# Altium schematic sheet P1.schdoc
size 420 x 297 mm; Width: 1655; Height: 1170; Symbol: Drawing-Symbol_A4; Company: 嘉立创EDA; Version: V1.0; Page Size: A4; @Project Name: C-T光谱仪; @Update Date: 2026-05-10; @Create Date: 2026-05-10; Device: Drawing-Symbol_A4; @Board Name: Board1; @Page Name: P1; @Create Time: 16:10:01; @Page Count: 1; @Page No: 1; @Schematic Name: Schematic2; @Update Time: 16:10:01; @Assembly Variant: Basic; Border: 1; Title Block Position: 3; Size: A4; Region Start: 1; X Region Count: 6; Y Region Count: 4; Blade Width: 10
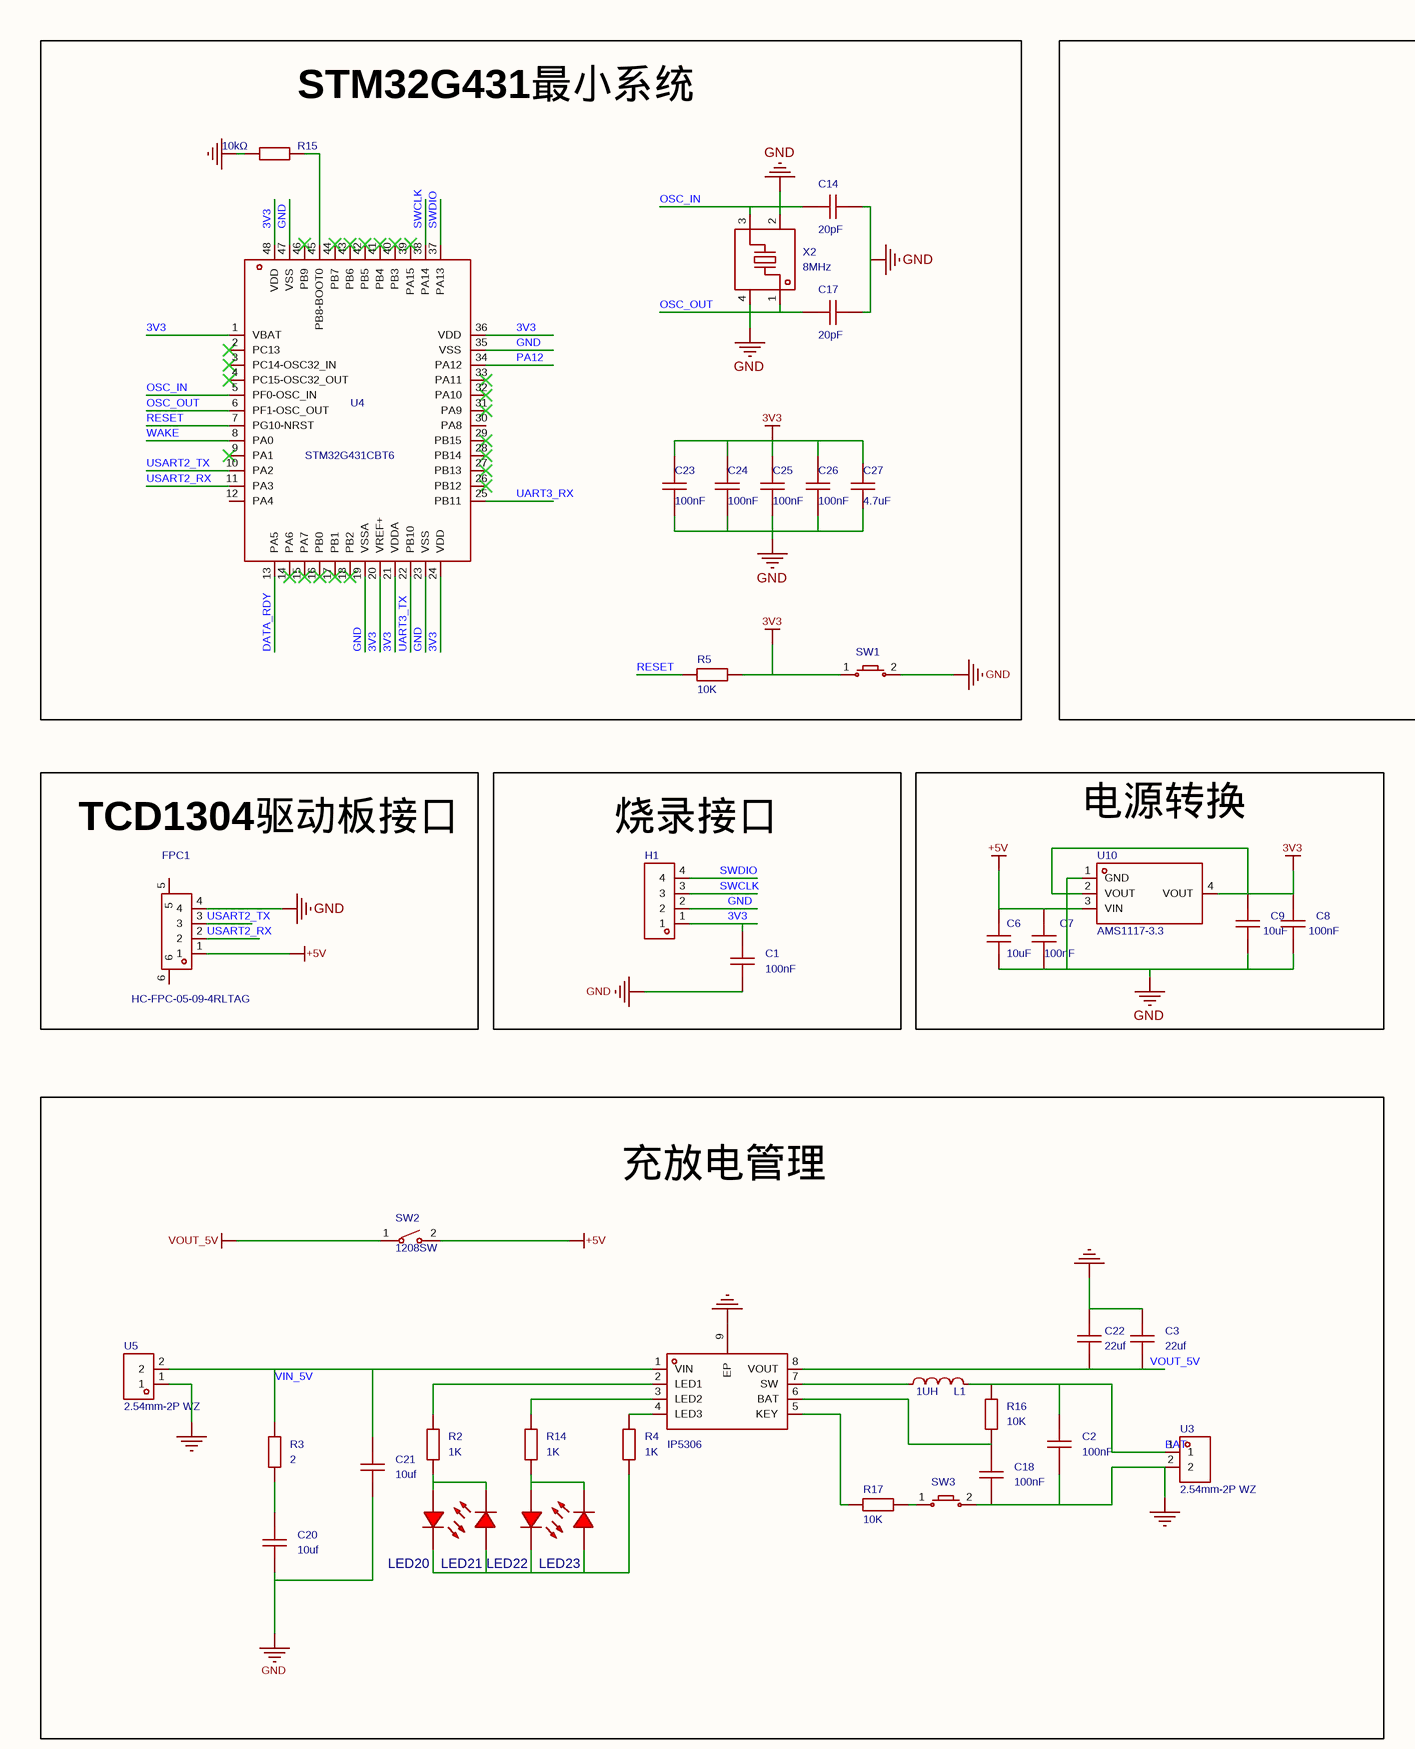
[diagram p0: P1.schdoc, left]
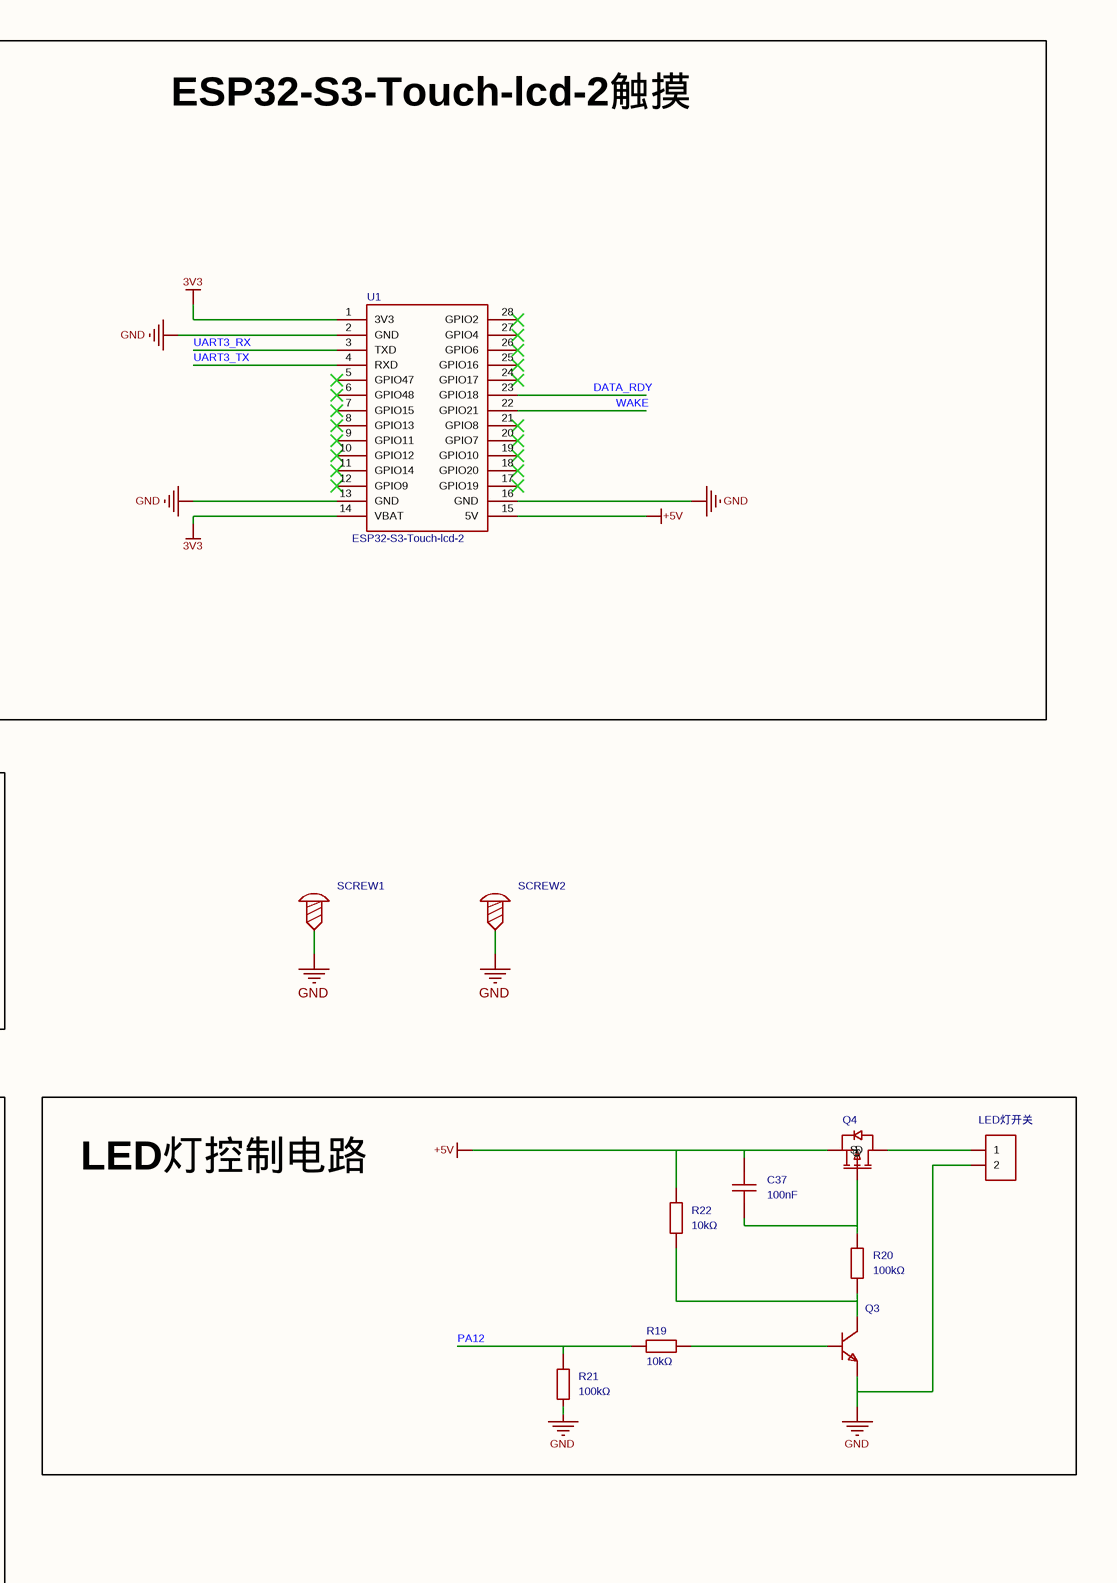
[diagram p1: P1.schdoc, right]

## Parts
C1  100nF  [C0805]
C2  100nF  [C0805]
C3  22uf  [C0805]
C6  10uF  [C0805]
C7  100nF  [C0805]
C8  100nF  [C0805]
C9  10uF  [C0805]
C14  20pF  [C0805]
C17  20pF  [C0805]
C18  100nF  [C0805]
C20  10uf  [C0805]
C21  10uf  [C0805]
C22  22uf  [C0805]
C23  100nF  [C0805]
C24  100nF  [C0805]
C25  100nF  [C0805]
C26  100nF  [C0805]
C27  4.7uF  [C0805]
C37  100nF  [C0805]
FPC1  HC-FPC-05-09-4RLTAG  [FPC-SMD_4P-P0.50_HC-FPC-05-09-4RLTAG]
H1  (no value)  [HDR-TH_4P-P2.54-V-M]
L1  1UH  [IND-SMD_L7.0-W6.6_CMKD-0630A]
LED20  (no value)  [LED_0805]
LED21  (no value)  [LED_0805]
LED22  (no value)  [LED_0805]
LED23  (no value)  [LED_0805]
LED灯开关  (no value)  [CONN-TH_2P-P2.50_HX-XH2.54-2PZZ-B]
Q3  (no value)  [S8050_SOT-23]
Q4  (no value)  [AO3401A_SOT-23-3]
R2  1K  [R0805]
R3  2  [R0805]
R4  1K  [R0805]
R5  10K  [R0805]
R14  1K  [R0805]
R15  10kΩ  [R0805]
R16  10K  [R0805]
R17  10K  [R0805]
R19  10kΩ  [R0805_1]
R20  100kΩ  [R0805_1]
R21  100kΩ  [R0805_1]
R22  10kΩ  [R0805_1]
SCREW1  (no value)  [M3螺丝]
SCREW2  (no value)  [M3螺丝]
SW1  (no value)  [Key_SMD_3x4x2]
SW2  1208SW  [SW-TH_L12.0-W8.0-P13.30_YT-1208-YD]
SW3  (no value)  [Key_SMD_3x4x2]
U1  (no value)  [ESP32-S3-LCD-2-20250122]
U2  IP5306  [ESOP-8_L4.9-W3.9-P1.27-LS6.0-BL-EP]
U3  2.54mm-2P WZ  [CONN-TH_2P-P2.50_HX-2.54MM-2P-WZ-1]
U4  STM32G431CBT6  [LQFP-48_L7.0-W7.0-P0.50-LS9.0-BL_1]
U5  2.54mm-2P WZ  [CONN-TH_2P-P2.50_HX-2.54MM-2P-WZ-1]
U10  AMS1117-3.3  [SOT-223-3_L6.5-W3.4-P2.30-LS7.0-BR]
X2  8MHz  [OSC-SMD_4P-L3.2-W2.5-BL]

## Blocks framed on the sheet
STM32G431最小系统: C14 C17 C23-C27 R5 R15 SW1 U4 X2
ESP32-S3-Touch-lcd-2触摸: U1
TCD1304驱动板接口: FPC1
烧录接口: C1 H1
电源转换: C6-C9 U10
充放电管理: C2 C3 C18 C20-C22 L1 LED20-LED23 R2-R4 R14 R16 R17 SW2 SW3 U2 U3 U5
LED灯控制电路: C37 LED灯开关 Q3 Q4 R19-R22

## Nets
3V3: C1.2 C8.2 C9.2 C23.2 C24.2 C25.2 C26.2 C27.2 H1.1 R5.2 SW1.1 U1.1(3V3) U1.14(VBAT) U4.1(VBAT) U4.20(VREF+) U4.21(VDDA) U4.24(VDD) U4.36(VDD) U4.48(VDD) U10.2(VOUT) U10.4(VOUT)
+5V: C6.2 C7.2 C37.2 FPC1.1 Q4.2(S) R22.2 SW2.2 U1.15(5V) U10.3(VIN)
GND: C1.1 C2.1 C3.2 C6.1 C7.1 C8.1 C9.1 C14.2 C17.2 C18.1 C20.1 C21.1 C22.2 C23.1 C24.1 C25.1 C26.1 C27.1 FPC1.4 H1.2 LED灯开关.2 Q3.2 R15.2 R21.1 SCREW1.1 SCREW2.1 SW1.2 SW3.2 U1.2(GND) U1.13(GND) U1.16(GND) U2.9(EP) U3.2 U4.19(VSSA) U4.23(VSS) U4.35(VSS) U4.47(VSS) U5.1 U10.1(GND) X2.2(GND) X2.4(GND)
VOUT_5V: C3.1 C22.1 SW2.1 U2.8(VOUT)
BAT: C2.2 L1.2 R16.2 U3.1
DATA_RDY: U1.23(GPIO18) U4.13(PA5)
OSC_IN: C14.1 U4.5(PF0-OSC_IN) X2.3
OSC_OUT: C17.1 U4.6(PF1-OSC_OUT) X2.1
PA12: R19.1 R21.2 U4.34(PA12)
RESET: R5.1 U4.7(PG10-NRST)
SWCLK: H1.3 U4.38(PA14)
SWDIO: H1.4 U4.37(PA13)
UART3_RX: U1.3(TXD) U4.25(PB11)
UART3_TX: U1.4(RXD) U4.22(PB10)
USART2_RX: FPC1.2 U4.11(PA3)
USART2_TX: FPC1.3 U4.10(PA2)
VIN_5V: C21.2 R3.2 U2.1(VIN) U5.2
WAKE: U1.22(GPIO21) U4.8(PA0)
NetC18_2: C18.2 R16.1 U2.6(BAT)
NetC20_2: C20.2 R3.1
NetC37_1: C37.1 Q4.1(G) R20.2
NetL1_1: L1.1 U2.7(SW)
NetLED20_1: LED20.1(C) LED21.2(A) LED22.1(C) LED23.2(A) R4.1
NetLED20_2: LED20.2(A) LED21.1(C) R2.1
NetLED22_2: LED22.2(A) LED23.1(C) R14.1
NetLED灯开关_1: LED灯开关.1 Q4.3(D)
NetQ3_1: Q3.1 R19.2
NetQ3_3: Q3.3 R20.1 R22.1
NetR2_2: R2.2 U2.2(LED1)
NetR4_2: R4.2 U2.4(LED3)
NetR14_2: R14.2 U2.3(LED2)
NetR15_1: R15.1 U4.45(PB8-BOOT0)
NetR17_1: R17.1 U2.5(KEY)
NetR17_2: R17.2 SW3.1

Not connected (* = marked no-connect by the designer): FPC1 5 6; U1 5(GPIO47)* 6(GPIO48)* 7(GPIO15)* 8(GPIO13)* 9(GPIO11)* 10(GPIO12)* 11(GPIO14)* 12(GPIO9)* 17(GPIO19)* 18(GPIO20)* 19(GPIO10)* 20(GPIO7)* 21(GPIO8)* 24(GPIO17)* 25(GPIO16)* 26(GPIO6)* 27(GPIO4)* 28(GPIO2)*; U4 2(PC13)* 3(PC14-OSC32_IN)* 4(PC15-OSC32_OUT)* 9(PA1)* 12(PA4) 14(PA6)* 15(PA7)* 16(PB0)* 17(PB1)* 18(PB2)* 26(PB12)* 27(PB13)* 28(PB14)* 29(PB15)* 30(PA8) 31(PA9)* 32(PA10)* 33(PA11)* 39(PA15)* 40(PB3)* 41(PB4)* 42(PB5)* 43(PB6)* 44(PB7)* 46(PB9)*

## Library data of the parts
C1 = CAP_0603: Symbol: Capacitance; 3D Model: ac125912035d415993ca9572d50418b10819f05c4eef4c71ace90d822a990e87; 3D Model Transform: 62.992,31.496,0,0,0,0,0,0,0; ConvertToPcb: yes; ModelName: C0603_L1.6-W0.8-H0.8
C2 C3 C18 C20-C22 C37 = CAP_0805: Symbol: Capacitance; 3D Model: 1ba041120af144c991958decab20d2410819f05c4eef4c71ace90d822a990e87; 3D Model Transform: 78.74,51.181,0,0,0,0,0,0.0005,0; ConvertToPcb: yes; ModelName: C0805_L2.0-W1.3-H1.3
C6 C9 = CL10A106KP8NNNC: 容值:10uF;精度:±10%;额定电压:10V;材质(温度系数):X5R;; Manufacturer: SAMSUNG(三星); Symbol: CL10A106KP8NNNC_1; 3D Model: ac125912035d415993ca9572d50418b1; 3D Model Transform: 62.992,31.496,0,0,0,0,0,0,0; Tolerance: ±10%; Voltage Rated: 10V; Temperature Coefficient: X5R; AddInBom: yes; ModelName: C0603_L1.6-W0.8-H0.8
C7 C8 C23-C26 = CC0603KRX7R9BB104: 容值:100nF;精度:±10%;额定电压:50V;材质(温度系数):X7R;; Manufacturer: YAGEO(国巨); Symbol: CC0603KRX7R9BB104_2; 3D Model: ac125912035d415993ca9572d50418b1; 3D Model Transform: 62.992,31.496,0,0,0,0,0,0,0; Tolerance: ±10%; Voltage Rated: 50V; Temperature Coefficient: X7R; AddInBom: yes; ModelName: C0603_L1.6-W0.8-H0.8
C14 C17 = 0603CG200J101NT: 容值:20pF;精度:±5%;额定电压:100V;材质(温度系数):C0G;额定电压(VAC):-;; Manufacturer: FH(风华); 3D Model: ac125912035d415993ca9572d50418b1; 3D Model Transform: 62.992,31.496,0,0,0,0,0,0,0; Tolerance: ±5%; Voltage Rated: 100V; Temperature Coefficient: C0G; AddInBom: yes; ModelName: C0603_L1.6-W0.8-H0.8
C27 = CL10A475KO8NNNC_1: 容值:4.7uF;精度:±10%;额定电压:16V;材质(温度系数):X5R;; Manufacturer: SAMSUNG(三星); 3D Model: ac125912035d415993ca9572d50418b1; 3D Model Transform: 62.992,31.496,0,0,0,0,0,0,0; Tolerance: ±10%; Voltage Rated: 16V; Temperature Coefficient: X5R; AddInBom: yes; ModelName: C0603_L1.6-W0.8-H0.8
FPC1 = HC-FPC-05-09-4RLTAG: 锁定特性:翻盖式;触点类型:双侧触点/上下接;触点数量:4P;间距:0.5mm;安装类型:卧贴;工作温度范围:-55℃~+85℃;焊接温度(最大值):-;; Manufacturer: HCTL(华灿天禄); 3D Model: e7843a06bd8d493d815c5f45a1277ceb0819f05c4eef4c71ace90d822a990e87; 3D Model Transform: 157.8737,137.795,0,0,0,0,0,-1.378,0; Locking Feature: 翻盖式; Number of Contacts: 4P; Pitch: 0.5mm; FFC, FCB Thickness: 0.3mm; AddInBom: yes
H1 = HDR-M_2.54_1x4P: Symbol: PZ254V-11-04P; 3D Model: 112f4d05e8d64e99ab9a333894bea4f90819f05c4eef4c71ace90d822a990e87; 3D Model Transform: 399.999,104.7242,0,0,0,0,0,0,-118.11; ConvertToPcb: yes; ModelName: HDR-TH_4P-P2.54-M-LI-1X4P
L1 = L_0805: Symbol: SDFL2012S100KTF; 3D Model: 37a81e68749a4138bd2dfa6897b24b850819f05c4eef4c71ace90d822a990e87; 3D Model Transform: 78.74,51.181,0,0,0,0,0,0.001,0; AddInBom: yes; ModelName: R0805_L2.0-W1.3-H0.6
LED20-LED23 = LED_0805-R: Symbol: LED_R; Convert to PCB: yes; 3D Model: 33fb9fca58e84f37a403ebeef4c28b770819f05c4eef4c71ace90d822a990e87; 3D Model Transform: 78.7,49.1,39.3,0,0,0,0,0,0; ModelName: LED-0805_R
LED灯开关 = HDR-F_2.54_1x2P: Symbol: Header-Female-2.54_1x2; 3D Model: a9450ef445564560a104363b9aacde4e0819f05c4eef4c71ace90d822a990e87; 3D Model Transform: 215.7476,98.425,0,0,0,0,0,0,-129.921; ConvertToPcb: yes; ModelName: HDR-TH_2P-P2.54-F-LI-1X2P
Q3 = S8050_SOT_NPN: Symbol: NPN; 3D Model: c62791f0466c4ae2a892c056b845b0ca0819f05c4eef4c71ace90d822a990e87; 3D Model Transform: 98.6,114.12,41.29,180,0,0,0,0,-3; ConvertToPcb: yes; ModelName: SOT-23-3P_L2.9-W1.3-H1.0-LS2.4-P0.95
Q4 = AO3401A_P: Symbol: P_MOS; 3D Model: c62791f0466c4ae2a892c056b845b0ca0819f05c4eef4c71ace90d822a990e87; 3D Model Transform: 98.6,114.12,41.29,180,0,0,0,0,0; AddInBom: yes; ModelName: SOT-23-3P_L2.9-W1.3-H1.0-LS2.4-P0.95
R2-R4 R14 R16 R17 = Res_0805: Symbol: 电阻_1; 3D Model: 37a81e68749a4138bd2dfa6897b24b85; 3D Model Transform: 78.74,51.181,0,0,0,0,0,-0.0005,0; ConvertToPcb: yes; ModelName: R0805_L2.0-W1.3-H0.6
R5 = Res_0603: Symbol: 电阻; 3D Model: fc143cca1e79419f9cd78b61e9279f080819f05c4eef4c71ace90d822a990e87; 3D Model Transform: 31.8897,63.7794,0,90,0,0,0,0,0; ConvertToPcb: yes; ModelName: R0603
R15 = 0603WAF1002T5E: 电阻类型:厚膜电阻;阻值:10kΩ;精度:±1%;功率:100mW;最大工作电压:75V;温度系数:±100ppm/℃;; Manufacturer: UNI-ROYAL(厚声); Symbol: 0603WAF1002T5E_2; 3D Model: fc143cca1e79419f9cd78b61e9279f08; 3D Model Transform: 31.8897,63.7794,0,90,0,0,0,0,0; Tolerance: ±1%; Power(Watts): 100mW; Overload Voltage (Max): 75V; AddInBom: yes; ModelName: R0603
R19-R22 = 电阻_Resistor: NGSpice Model: 169a2b7a081142ae9cb8aebabf32e595; Sim Model: 8be60972bfca48309599b114ee1ccaf4; Sim Model Path: 0819f05c4eef4c71ace90d822a990e87; AddInBom: yes
SCREW1 SCREW2 = M3螺丝: Symbol: 螺丝孔; ConvertToPcb: yes
SW1 SW3 = Key_SMD_3x4x2: Symbol: 轻触按键x2; 3D Model: 63599cce708d48afbce1b0db003544770819f05c4eef4c71ace90d822a990e87; 3D Model Transform: 196.85,114.17,79.13,0,0,0,0,0,0; ConvertToPcb: yes; ModelName: SW-SMD_L4.0-W2.9-H2-LS5.0
SW2 = 1208SW: 3D Model: d4db5ef8f5de46b78cf99ec7bd88eb950819f05c4eef4c71ace90d822a990e87; 3D Model Transform: 531.495,315.3537,0,0,0,0,0,0,-118.11; AddInBom: yes
U1 = ESP32-S3-Touch-lcd-2: Symbol: 微雪ESP32-S3R8开发板; AddInBom: yes
U2 = IP5306: 2.1A充电2.4A放电高集成度移动电源SOC; Manufacturer: INJOINIC(英集芯); 3D Model: d3e00daa36c445139c055a3b9efb85d2; 3D Model Transform: 240.157,192.913,0,90,0,0,0,0,0; AddInBom: yes; ModelName: ESOP-8_L4.9-W3.9-H1.6-LS6.0-P1.27
U3 U5 = 2.54mm-2P WZ: 插针结构:1x2P;间距:2.5mm;安装方式:弯插;参考系列:XH;总PIN数:2P;排数:1;每排PIN数:2;行距:-;额定电流:3A;触头材质:黄铜;触头镀层:锡;工作温度:-25℃~+85℃;; Manufacturer: SHOU HAN(首韩); AddInBom: yes; ModelId: 2ebc50b0ba21408186ff3e2f0d568de60819f05c4eef4c71ace90d822a990e87; ModelTransform: 295.669,299.212,0,0,0,0,0,-137.795,-137.795; Pins Structure: 1x2P; Pitch: 2.5mm; Reference Series: XH; Number of PINs Per Row: 2; Current Rating: 3A; Voltage Rating: 250V; Plastic Material: PA66; Flame Retardant Rating: UL94V-0
U4 = STM32G431CBT6: CPU内核:ARM-M系列;CPU最大主频:170MHz;程序存储容量:128KB;程序存储器类型:FLASH;RAM总容量:32KB;GPIO端口数量:38;; Manufacturer: ST(意法半导体); EEPROM: 128KB; 3D Model: 093be70396ff421eb2cdb946d5311efc; 3D Model Transform: 354.331,354.331,0,0,0,0,0,0,0; CPU Maximum Speed: 170MHz; Operating Voltage Range: 1.71V~3.6V; Program Memory Type: FLASH; RAM Size: 32KB; GPIO Ports Number: 38; ADC (Bit): 12bit; Peripheral/Function: DMA；PWM; Watchdog: 有; AddInBom: yes; ModelName: LQFP-48_L7.0-W7.0-H1.4-LS9.0-P0.50
U10 = AMS1117-3.3_C6186: 输出类型:固定;工作电压:-;输出电压:3.3V;输出电流:1A;电源纹波抑制比(PSRR):72dB@(120Hz);输出极性:正极;; Manufacturer: AMS; 3D Model: 925194bf9823436183a3e0b978a8d076; 3D Model Transform: 279.89794,255.905,0,180,0,0,-3.9385,-0.0005,0; Output Type: 固定; Output Voltage: 3.3V; Output Current: 1A; Voltage Dropout: 1.3V@(800mA); Output Configuration: 正极; Number of Outputs: 1; AddInBom: yes; ModelName: SOT-223-4P_L6.5-W3.5-H1.6-LS7.0-P2.30
X2 = 3225-8.00-10-10-10/A: 晶振类型:贴片无源晶振;频率:8MHz;频率公差:±10ppm;频率稳定度:-;负载电容:10pF;工作温度:-;; Manufacturer: LIMING(利明); 3D Model: ae22b8d143894765bc8100c37cb6356f; 3D Model Transform: 125.984,98.425,0,0,0,0,0,0,0; Crystal Type: 贴片无源晶振; Frequency Tolerance: ±10ppm; Load Capacitance: 10pF; AddInBom: yes; ModelName: OSC-SMD_4P-L3.2-W2.5-H1.0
